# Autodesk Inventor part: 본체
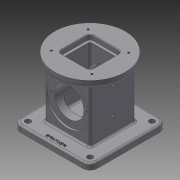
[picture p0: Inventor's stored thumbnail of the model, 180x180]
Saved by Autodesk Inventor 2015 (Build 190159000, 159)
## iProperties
Created: 2021-05
Part Number: 본체
Material: 일반
Document SubType Name: Modeling
Designer: 101654789
Density: 1 g/cm^3
Appearance: 기본값
Author: 101654789
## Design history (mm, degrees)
sketch "스케치4"
  geometry: C1 r 57.5 at (0, 0); 1 further point
  constraints: 1 centre point, 1 coincident
  dimensions: "d3" = 115 diameter of C1
extrude "돌출2" new body sketch "스케치4" distance "d4" = 10; taper "d5" = 0 deg
sketch "스케치5"
  geometry: L1 (-37, -37)-(37, -37); L2 (37, -37)-(37, 37); L3 (37, 37)-(-37, 37); L4 (-37, 37)-(-37, -37); L5 (-37, -37)-(37, 37); L6 (37, -37)-(-37, 37); C1 r 57.5 at (0, 0) reference
  constraints: 12 end point, 2 midpoint, 2 parallel, 1 horizontal, 1 perpendicular
  dimensions: "d6" = 74 distance of L3.end L2.end; "d7" = 74 distance of L1.end L2.end
extrude "돌출3" join sketch "스케치5" distance "d8" = 98; taper "d9" = 0 deg
sketch "스케치6"
  geometry: L1 (-37, -37)-(37, -37) reference; L2 (37, -37)-(37, 37) reference; L3 (37, 37)-(-37, 37) reference; L4 (-37, 37)-(-37, -37) reference; L5 (-62.5, -62.5)-(62.5, -62.5); L6 (62.5, -62.5)-(62.5, 62.5); L7 (62.5, 62.5)-(-62.5, 62.5); L8 (-62.5, 62.5)-(-62.5, -62.5); L9 (-62.5, -62.5)-(62.5, 62.5); L10 (62.5, -62.5)-(-62.5, 62.5); 1 further point
  constraints: 12 end point, 2 midpoint, 2 parallel, 1 horizontal, 1 perpendicular
  dimensions: "d10" = 125 distance of L6.end L7.end; "d11" = 125 distance of L5.end L6.end
extrude "돌출4" join sketch "스케치6" distance "d12" = 10; taper "d13" = 0 deg
sketch "스케치7"
  geometry: L1 (99.5, -98)-(-25.5, -98) reference; L2 (94.5, 10)-(-20.5, 10) reference; C1 r 35 at (37, -44); 2 further points
  constraints: 1 centre point, 1 midpoint, 1 vertical alignment
  dimensions: "d14" = 70 diameter of C1; "d15" = 54 distance from line of C1.centre L2
extrude "돌출5" cut sketch "스케치7" distance "d16" = 3; taper "d17" = 0 deg
sketch "스케치8"
  geometry: C1 r 35 at (0, 0) reference; C2 r 24 at (0, 0); 1 further point
  constraints: 1 centre point, 1 coincident
  dimensions: "d18" = 48 diameter of C2
extrude "돌출6" cut sketch "스케치8" stored distance "d19" = 48 (= d18); taper "d20" = 0 deg
sketch "스케치9"
  geometry: C1 r 24 at (37, 44) reference; C2 r 35 at (37, 44); 1 further point
  constraints: 1 centre point, 1 coincident
  dimensions: "d21" = 70 diameter of C2
extrude "돌출7" cut sketch "스케치9" distance "d22" = 3; taper "d23" = 0 deg
sketch "스케치10"
  geometry: L1 (-26, 26)-(26, 26); L2 (26, 26)-(26, -26); L3 (26, -26)-(-26, -26); L4 (-26, -26)-(-26, 26); L5 (-26, 26)-(26, -26); L6 (26, 26)-(-26, -26); C1 r 57.5 at (0, 0) reference
  constraints: 12 end point, 2 midpoint, 2 parallel, 1 horizontal, 1 perpendicular
  dimensions: "d24" = 52 distance of L2.end L3.end; "d25" = 52 distance of L1.end L2.end
extrude "돌출8" cut sketch "스케치10" distance "d26" = 8; taper "d27" = 0 deg
sketch "스케치11"
  geometry: L1 (-22, 22)-(22, 22); L2 (22, 22)-(22, -22); L3 (22, -22)-(-22, -22); L4 (-22, -22)-(-22, 22); L5 (-22, 22)-(22, -22); L6 (22, 22)-(-22, -22); 1 further point
  constraints: 12 end point, 2 midpoint, 2 parallel, 1 horizontal, 1 perpendicular
  dimensions: "d28" = 44 distance of L2.end L3.end; "d29" = 44 distance of L1.end L2.end
extrude "돌출9" cut sketch "스케치11" distance "d30" = 74; taper "d31" = 0 deg
sketch "스케치12"
  geometry: C1 r 28 at (0, 0); 1 further point
  constraints: 1 centre point, 1 coincident
  dimensions: "d32" = 56 diameter of C1
extrude "돌출10" cut sketch "스케치12" distance "d33" = 18; taper "d34" = -10 deg
sketch "스케치13"
  geometry: L1 (0, 0)-(0, 29); C1 r 35 at (0, 0) reference; 1 further point
  constraints: 2 end point, 1 vertical
  dimensions: "d35" = 29 distance of L1.start L1.end
hole "구멍1" sketch "스케치13" at (0, 29) diameter "d36" = 3.242; stored, may be unused: countersink angle "d40" = 90 deg, drill point angle "d42" = 118 deg; dims "d37" = 8, "d38" = 4, "d39" = 2, "d41" = 10
sketch "스케치14"
  geometry: C1 r 57.5 at (0, 0) reference; 4 further points
  constraints: 2 horizontal alignment
  dimensions: "d46" = 30 vertical distance of C1.centre point (-33, 30); "d47" = 60 distance of point (-33, -30) point (-33, 30); "d48" = 66 distance of point (33, 30) point (-33, 30); "d49" = 66 distance of point (33, -30) point (-33, -30); "d57" = 33 horizontal distance of C1.centre point (-33, 30); "d58" = 33 horizontal distance of C1.centre point (-33, -30)
hole "구멍2" sketch "스케치14" at (-33, 30), (33, 30), (-33, -30), (33, -30) diameter "d50" = 3.242; stored, may be unused: countersink angle "d54" = 90 deg, drill point angle "d56" = 118 deg; dims "d51" = 8, "d52" = 4, "d53" = 2, "d55" = 10
sketch "스케치15"
  geometry: L1 (98, 99.5)-(98, -25.5) reference; 4 further points
  constraints: 2 horizontal alignment, 1 midpoint
  dimensions: "d59" = 37 distance from line of L1 point (61, 37); "d60" = 43 distance of point (18, 37) point (61, 37)
hole "구멍3" sketch "스케치15" at (61, 37), (18, 37) diameter "d61" = 4.134; stored, may be unused: countersink angle "d65" = 90 deg, drill point angle "d67" = 0 deg; dims "d62" = 10, "d63" = 4, "d64" = 2, "d66" = 20
fillet "모깎기1" dims "d68" = 12
hole "구멍4" diameter "d71" = 9; stored, may be unused: countersink angle "d75" = 90 deg, drill point angle "d77" = 0 deg; dims "d69" = 10, "d70" = 10, "d72" = 10, "d73" = 4, "d74" = 2, "d76" = 20
hole "구멍5" diameter "d80" = 9; stored, may be unused: countersink angle "d84" = 90 deg, drill point angle "d86" = 0 deg; dims "d78" = 10, "d79" = 10, "d81" = 10, "d82" = 4, "d83" = 2, "d85" = 20
hole "구멍6" diameter "d89" = 9; stored, may be unused: countersink angle "d93" = 90 deg, drill point angle "d95" = 0 deg; dims "d87" = 10, "d88" = 10, "d90" = 10, "d91" = 4, "d92" = 2, "d94" = 20
hole "구멍7" diameter "d98" = 9; stored, may be unused: countersink angle "d102" = 90 deg, drill point angle "d104" = 0 deg; dims "d96" = 10, "d97" = 10, "d99" = 10, "d100" = 4, "d101" = 2, "d103" = 20
fillet "모깎기2" dims "d105" = 3
fillet "모깎기3" dims "d106" = 3
fillet "모깎기4" dims "d107" = 3
fillet "모깎기5" dims "d108" = 6
chamfer "모따기1" distance "d109" = 1; stored, may be unused: second distance "d110" = 2, angle "d111" = 45 deg
fillet "모깎기6" dims "d112" = 3
fillet "모깎기7" dims "d113" = 3
fillet "모깎기8" dims "d114" = 3
fillet "모깎기9" dims "d115" = 3
sketch "스케치16"
  geometry: 2 further points
  constraints: 1 vertical alignment, 1 other
  dimensions: "d117" = 55 distance of point (0, -55) point (0, 0)
feature "엠보싱1" sketch "스케치16" dims "d3" = 115, "d118" = 0.5, "d119" = 0
fillet "모깎기10" dims "d120" = 3
fillet "모깎기11" dims "d121" = 3
node "솔리드2"
pattern_circular "원형 패턴1" dims angle "d44" = 360 deg
mirror "대칭1"
